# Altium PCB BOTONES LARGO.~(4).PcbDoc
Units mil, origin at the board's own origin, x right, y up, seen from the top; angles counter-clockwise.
Board outline 2200 x 1100 mil, 2 copper layers (Top Layer, Bottom Layer), stack 65.792 mil thick; 14 components, 13 nets, 34 pads, 0 vias.
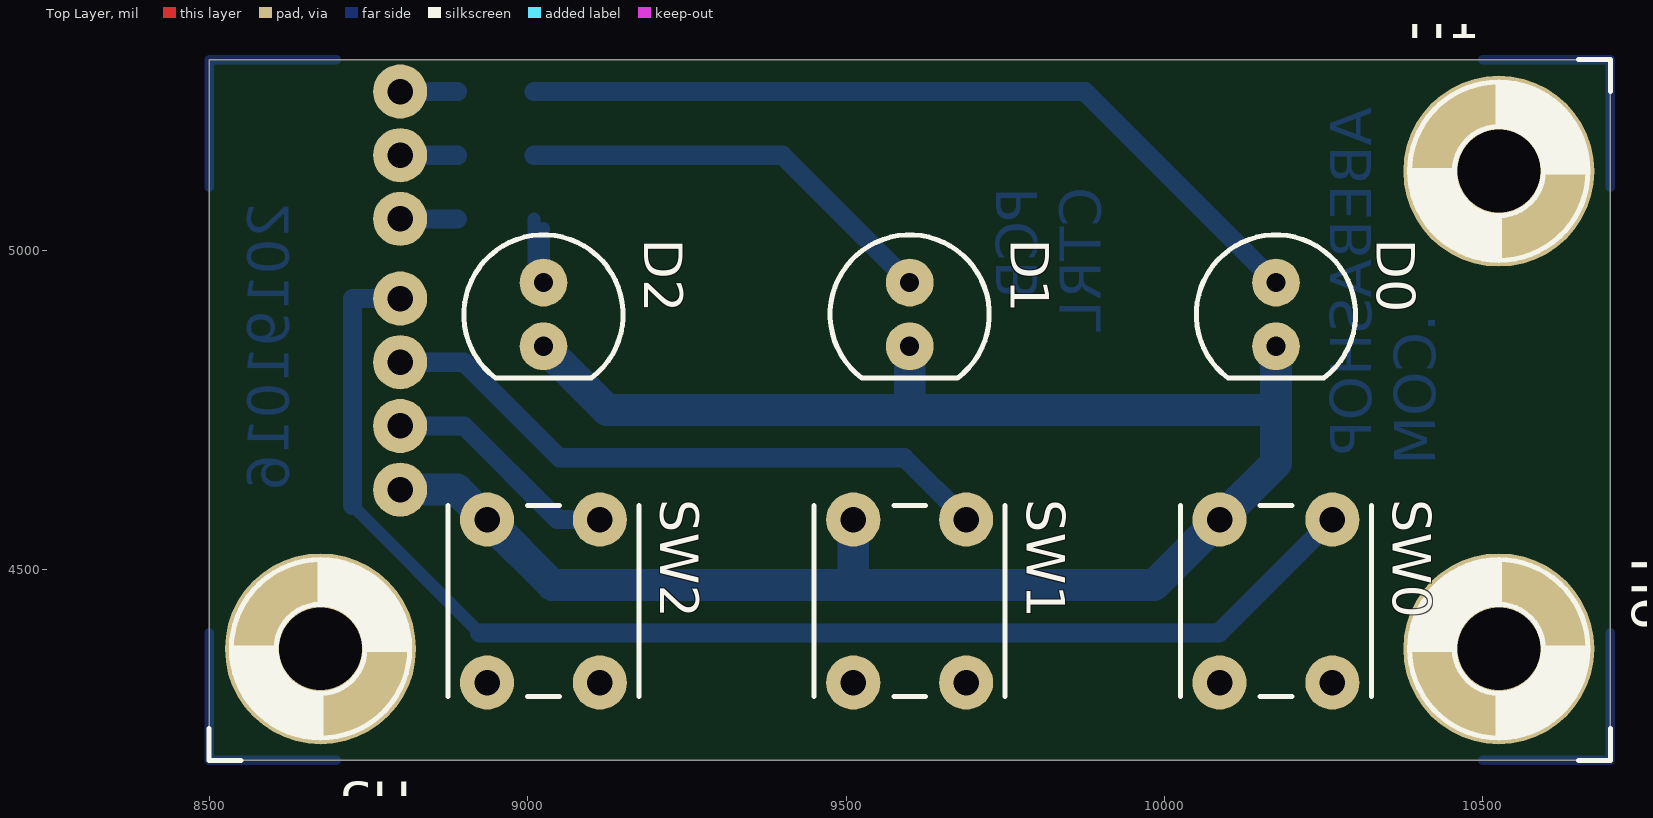
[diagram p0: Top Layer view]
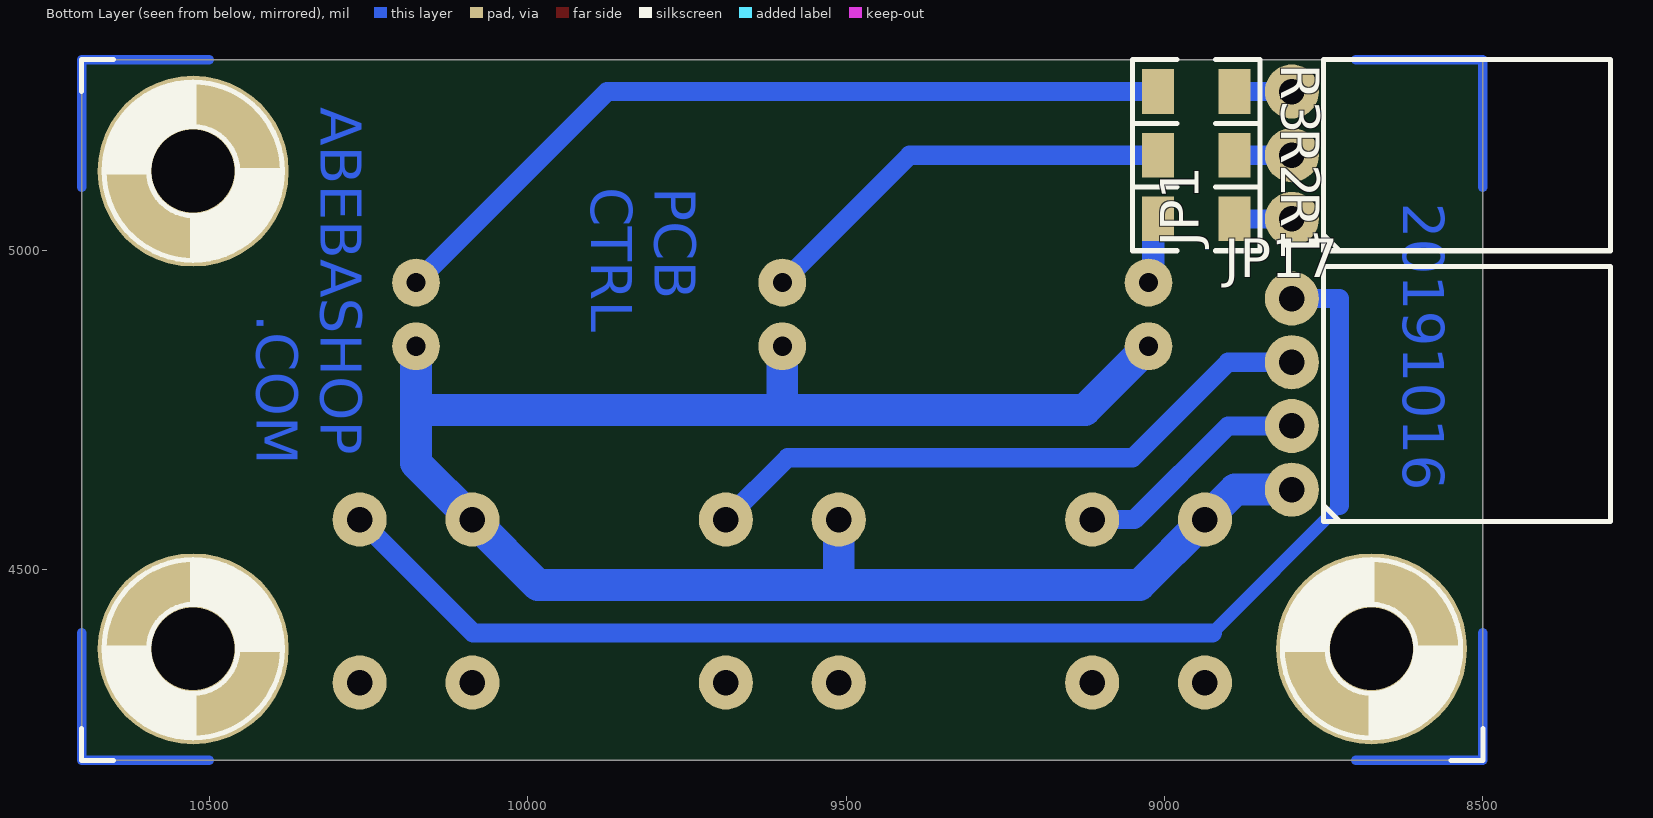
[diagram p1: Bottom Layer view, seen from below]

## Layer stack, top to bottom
Top Layer: signal copper 1.4
Dielectric: core 62.9921, FR-4, Dk 4.8
Bottom Layer: signal copper 1.4

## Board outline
8500,4200 10700,4200 10700,5300 8500,5300

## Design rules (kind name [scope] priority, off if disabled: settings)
Clearance [All] p1: gap=10
PolygonConnect [All] p1: connectstyle=Relief reliefconductorwidth=10 reliefentries=4 polygonreliefangle="90 Angle"
RoutingVias [All] p1: holewidth=28 width=50 viastyle="Through Hole" minholewidth=28 minwidth=50 maxholewidth=28 maxwidth=50
SilkscreenOverComponentPads [All] p1: minsilkscreentomaskgap=10
SolderMaskExpansion [All] p1: expansion=4
Width [All] p1: maxlimit=100 minlimit=10 preferedwidth=10
27 further rules are at their usual default settings.

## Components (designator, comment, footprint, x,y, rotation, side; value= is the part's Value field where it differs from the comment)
D0 "Led 5mm Rojo Difuso" "LED5mm ROJO" 10175,4900 r270 top
D1 "Led 5mm Rojo Difuso" "LED5mm ROJO" 9600,4900 r270 top
D2 "Led 5mm Rojo Difuso" "LED5mm ROJO" 9025,4900 r270 top
H1 "Agujero de Montaje" agujero 10525,5125 r0 top
H5 "Agujero de Montaje" agujero 8675,4375 r180 top
H6 "Agujero de Montaje" agujero 10525,4375 r270 top
JP1 "Header3x1" CONPOL3X1_90 8800,5100 r90 bottom
JP17 "Header4x1" CONPOL4X1_90 8800,4625 r90 bottom
R1 "Res" 1206NP 8950,5050 r180 bottom
R2 "Res" 1206NP 8950,5150 r180 bottom
R3 "Res" 1206NP 8950,5250 r180 bottom
SW0 "SW_T_5MM" SW_T_5MM 10175,4450 r270 top
SW1 "SW_T_5MM" SW_T_5MM 9600,4450 r270 top
SW2 "SW_T_5MM" SW_T_5MM 9025,4450 r270 top

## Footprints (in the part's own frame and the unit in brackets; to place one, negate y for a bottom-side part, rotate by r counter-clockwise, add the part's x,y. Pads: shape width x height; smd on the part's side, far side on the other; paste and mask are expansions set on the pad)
1206NP [mil]
  rect 50x70 smd: 1(-60,0) 2(60,0)
  silkscreen extent -100,-50 100,50
agujero [mil] "AGUJERO DE MONTAJE"
  round 300 hole 130: 1(0,0)
  silkscreen extent -140,-140 175,175
CONPOL3X1_90 [mil] "CONECTOR POLARIZADO 3x1"
  round 85 hole 40: 1(-50,0) 2(50,0) 3(150,0)
  silkscreen extent -100,-500 200,-50, body extent -100,-491 200,14, height 250
CONPOL4X1_90 [mil]
  round 85 hole 40: 1(0,0) 2(100,0) 3(200,0) 4(300,0)
  silkscreen extent -50,-500 350,-50, body extent -50,-491 350,14, height 250
"LED5mm ROJO" [mil] "LED 5MM"
  round 75 hole 30: 1(-50,0) 2(50,0)
  silkscreen extent -125,-125 100,125, body extent -116,-116 99,116, height 339
SW_T_5MM [mil] "PULSADOR DE 2 CONTACTOS, 4 TERMINALES"
  round 85 hole 40: 1(127.95,-88.58) 2(127.95,88.58) 3(-127.95,-88.58) 4(-127.95,88.58)
  silkscreen extent -150,-150 150,150, body extent -152,-119 152,119, height 197

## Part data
JP1: "Header 3x1"
JP17: "Header 4x1"
R1 R2 R3: "Resistor"

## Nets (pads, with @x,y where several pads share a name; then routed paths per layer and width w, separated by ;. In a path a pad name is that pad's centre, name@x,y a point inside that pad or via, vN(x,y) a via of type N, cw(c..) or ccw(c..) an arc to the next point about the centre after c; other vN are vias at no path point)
"BUS CS1": JP1.1 R1.2 | length 90
  Bottom Layer w30: JP1.1 R1.2
"BUS CS2": JP1.2 R2.2 | length 90
  Bottom Layer w30: JP1.2 R2.2
"BUS CS3": JP1.3 R3.2 | length 90
  Bottom Layer w30: JP1.3 R3.2
GND: D0.2 D1.2 D2.2 JP17.1 SW0.3 SW1.3 SW2.3 | length 3094.3
  Bottom Layer w50: JP17.1 8889.37,4625 SW2.3 9039.37,4475 9511.42,4475 ; D2.2 9125,4750 9600,4750 ; SW1.3 9511.42,4475 ; D1.2 9600,4750 ; D0.2 10175,4750 ; 9511.42,4475 9983.46,4475 SW0.3 10175,4666.54 10175,4750 ; 9600,4750 10175,4750
NetD0_1: D0.1 R3.1 | length 1289.3
  Bottom Layer w30: R3.1 9875,5250 D0.1
NetD1_1: D1.1 R2.1 | length 672.8
  Bottom Layer w30: R2.1 9400,5150 D1.1
NetD2_1: D2.1 R1.1 | length 170
  Bottom Layer w20: D2.1@9010,4965 R1.1 ; D2.1 R1.1@9025,5035
SW0: JP17.4 SW0.4 | length 2495.1
  Bottom Layer w20: JP17.4 8725,4925 8725,4600 8925,4400
  Bottom Layer w30: 8725,4600 8725,4925 JP17.4 ; 8925,4400 10085.63,4400 SW0.4
SW0_: SW0.2
SW1: JP17.3 SW1.4 | length 990.9
  Bottom Layer w30: JP17.3 8900,4825 9050,4675 9591.54,4675 SW1.4
SW1_: SW1.2
SW2: JP17.2 SW2.4 | length 374.5
  Bottom Layer w30: JP17.2 8900,4725 9047.05,4577.95 SW2.4
SW2_: SW2.2
pads on no net: H1.1 H5.1 H6.1 SW0.1 SW1.1 SW2.1
copper on no net: | length 1600
  Bottom Layer w15: 8500,4400 8500,4200 8700,4200 ; 8500,5100 8500,5300 8700,5300 ; 10500,4200 10700,4200 10700,4400 ; 10500,5300 10700,5300 10700,5100

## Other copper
Bottom Layer:
  text "ABEBASHOP" at 10325,5225 h65 r90
  text "PCB" at 9800,5100 h65 r90
  text "CTRL" at 9900,5100 h65 r90
  text "20191016" at 8625,5075 h65 r90
  text ".COM" at 10425,4900 h65 r90

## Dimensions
10525,4375 to 10175,4325 on Top Overlay
10525,4375 to 10200,4900 on Top Overlay
10525,4375 to 10275,4450 on Top Overlay
10525,4375 to 10525,5125 on Top Overlay
10525,4375 to 8675,4375 on Top Overlay
10525,5125 to 10700,5300 on Top Overlay
8500,5300 to 10525,5125 on Top Overlay
8500,4200 to 8500,5300 on Top Overlay
8936.42,4577.95 to 9511.42,4577.95 on Top Overlay
8500,4200 to 10700,4200 on Top Overlay
9511.42,4577.95 to 10086.42,4577.95 on Top Overlay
